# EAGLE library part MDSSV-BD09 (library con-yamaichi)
YAMAICHI CONNECTOR
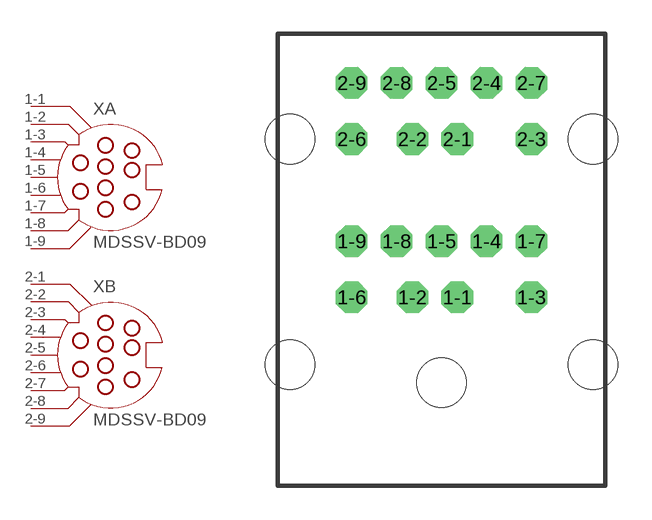
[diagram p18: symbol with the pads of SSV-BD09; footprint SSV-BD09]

Designator prefix X; gates A=SSV-BC09 B=SSV-BC09

## MDSSV-BD09 (OC_FARNELL: unknown; OC_NEWARK: unknown)  [SSV-BD09]
1-1  A:1  pas
1-2  A:2  pas
1-3  A:3  pas
1-4  A:4  pas
1-5  A:5  pas
1-6  A:6  pas
1-7  A:7  pas
1-8  A:8  pas
1-9  A:9  pas
2-1  B:1  pas
2-2  B:2  pas
2-3  B:3  pas
2-4  B:4  pas
2-5  B:5  pas
2-6  B:6  pas
2-7  B:7  pas
2-8  B:8  pas
2-9  B:9  pas

## Footprint SSV-BD09 (pad centres in mm)
Mini Din YAMAICHI CONNECTOR
drill 0.9 octagon: 1-1 0.7,8.5; 1-2 -1.3,8.5; 1-3 4,8.5; 1-4 2,11; 1-5 0,11; 1-6 -4,8.5; 1-7 4,11; 1-8 -2,11; 1-9 -4,11; 2-1 0.7,15.55; 2-2 -1.3,15.55; 2-3 4,15.55; 2-4 2,18.05; 2-5 0,18.05; 2-6 -4,15.55; 2-7 4,18.05; 2-8 -2,18.05; 2-9 -4,18.05
hole 2.2 at -6.75,5.5
hole 2.2 at 0,4.7
hole 2.2 at 6.75,5.5
hole 2.2 at -6.75,15.55
hole 2.2 at 6.75,15.55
